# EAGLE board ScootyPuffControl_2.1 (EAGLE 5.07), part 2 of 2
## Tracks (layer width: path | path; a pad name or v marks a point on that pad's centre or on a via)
+5V  (via drill 0.41 pad 0.81, 0.61 pad 0.81)
  Top 0.254: R110.2 83.4,35.24 v81.92,35.24 | IC102.19 102.29,25.35 107,20.64 107,16.51 106.36,15.88 100.97,15.88 100.33,15.24 | 83.72,22.54 R310.2
  Top 0.305: R111.2 R112.2 R113.2 R108.2 R109.2 R110.2 | v85.09,27.3 81.92,27.3 81.28,26.67 81.28,26.04 79.75,24.5 IC305.8 79.75,22.54 | IC305.7 79.09,22.54 79.75,22.54 | 79.75,22.54 83.72,22.54 | R309.2 74.83,20.74 73.66,21.91 73.34,21.91
  Top 0.406: IC303.1 64.77,43.82 63.82,44.77 62.55,44.77 61.91,44.13 61.01,44.13 C306.2 60.59,43.81 v58.74,43.81
  Top 0.61: C306.2 60.28,44.13 | J100.P$36 99.06,92.71 v97.79,92.71 96.52,92.71 J100.P$34 | v101.6,81.28 99.69,79.38 99.69,55.24 v97.16,52.7 | J103.P$6 100.33,15.24 99.06,16.51 99.06,26.67 98.42,27.3 v97.16,27.3 88.27,27.3 IC301.4 | J102.P$6 54.61,15.24 55.24,15.88 60.96,15.88 61.59,16.51 v61.59,20.95 62.23,21.59 73.03,21.59 73.34,21.91 73.66,22.23 73.66,28.57 76.2,31.11 81.92,31.11 83.19,29.84 83.14,29.84 C305.+
  Top 1.016: IC301.2 88.27,27.3 88.27,28.57 | 88.27,28.57 IC301.4 | C305.+ 85.13,29.8 86.36,28.57 88.27,28.57
  Bottom 0.305: R304.2 78.72,56.52 77.79,56.52 77.15,57.15 75.56,57.15 72.39,53.98 69.22,53.98 65.41,50.16 60.64,50.16 58.74,48.26 v58.74,43.81
  Bottom 0.406: v90.81,29.21 92.08,29.21 92.08,29.84 | v58.74,43.81 59.69,42.86 59.69,40.64 58.42,39.37 58.42,28.57 57.15,27.3 57.15,23.81 59.69,20.95 v61.59,20.95
  Bottom 0.61: v97.79,92.71 100.33,92.71 101.6,91.44 v101.6,81.28 | v97.16,27.3 v97.16,52.7
  Bottom 1.016: 80.64,25.4 80.64,42.23 91.44,42.23 91.44,29.84 92.08,29.84 99.69,29.84 99.69,25.4 80.64,25.4
  other vias: 85.09,29.21 87,27.3 88.9,27.3 90.81,27.3 87,29.21 88.9,29.21
  pour Top (isolate 0.61, no thermals): 99.69,21.91 85.41,21.91 85.41,23.81 81.28,23.81 81.28,32.07 99.69,32.07
  pour Bottom: 80.64,26.04 80.64,41.91 90.81,41.91 90.81,29.84 91.44,29.21 99.06,29.21 99.06,26.04
+12V  (via drill 0.41 pad 0.81, 0.61 pad 0.81)
  Top 0.61: IC201.5 37.15,19.68 37.47,19.37 37.47,13.97 C201.2 D201.A 35.1,12.24 | IC221.5 36.83,76.83 37.47,76.2 37.47,71.53 C221.2 D221.A 34.92,70.94 33.66,69.85 v26.67,69.85 | v26.67,41.27 33.66,41.27 35.1,42.73 D211.A C211.2 37.47,42.77 37.47,47.62 36.83,48.26 IC211.5 | v26.67,14.61 29.21,12.06 34.92,12.06 35.1,12.24 | D6.A 113.48,95.3 C251.2 | IC231.5 123.19,36.83 122.56,37.47 122.56,41.68 C241.2 D231.A 124.92,43.63 125.41,44.13 v133.67,44.13 | 124.78,71.12 C231.2 122.56,70.89 122.56,66.04 123.19,65.41 IC241.5 | 124.78,71.12 D5.A | IC251.5 123.19,93.98 122.56,94.61 v122.56,97.79 | v133.67,72.71 125.09,72.71 124.78,72.39 124.78,71.12 | 35.1,12.24 35.1,12.06 43.18,12.06 43.18,12.7 C261.+ 43.2,14.63 43.81,15.24 50.8,15.24 52.07,13.97 v52.07,12.06 | 123.8,12.06 C262.+ 125.12,12.06 | v62.87,13.34 62.87,20 63.5,20.64 73.66,20.64 74.3,20 74.3,13.97 74.93,13.34 J303.6 77.47,15.24 78.11,15.88 81.92,15.88 82.55,15.24 J303.2
  Top 1.016: D6.A v111.76,97.79 93.98,97.79 | J100.P$30 91.44,97.79 93.98,97.79 | 93.98,97.79 J100.P$32 | v107.95,12.06 123.8,12.06 | v133.67,13.34 132.4,12.06 125.12,12.06 | v97.16,13.34 97.16,19.68 96.52,20.32 | 96.52,20.32 87,20.32 85.72,19.05 85.72,13.97 85.09,13.34 J303.2 | R303.2 96.37,22.07 96.52,21.59 96.52,20.32
  Bottom 0.61: v26.67,69.85 v26.67,41.27 v26.67,14.61 | 122.56,98.74 v122.56,97.79 | v62.87,13.34 53.34,13.34 v52.07,12.06
  Bottom 1.016: v133.67,13.34 v133.67,44.13 v133.67,72.71 133.67,97.47 132.4,98.74 122.56,98.74 112.71,98.74 v111.76,97.79 | v107.95,12.06 106.68,13.34 106.05,13.34 v97.16,13.34
AD0
  Top 0.254: IC101.98 67.94,64.68 67.94,73.03 | IC108.1 70.17,83.39 70.17,82.87 69.85,82.55 69.22,82.55 68.88,82.22 IC108.4 68.88,79.95 C117.1 69.93,79.61 70.17,79.38 70.17,77.15 67.94,74.93 67.94,73.03 | 67.94,73.03 67.94,73.34
AD1
  Top 0.254: IC101.99 67.31,64.61 67.31,76.52 67.63,76.83 67.63,79.38 67.39,79.61 C116.1 66.58,79.71 66.34,79.71 IC107.4 66.34,82.22 66.67,82.55 67.31,82.55 67.63,82.87 67.63,83.39 IC107.1
AD2
  Top 0.254: IC101.100 66.67,64.54 66.67,75.88 65.09,77.47 65.09,79.38 64.85,79.61 C115.1 63.8,79.95 IC106.4 63.8,82.22 64.14,82.55 64.77,82.55 65.09,82.87 65.09,83.39 IC106.1
AD3
  Top 0.254: IC101.1 69.62,57.78 67.94,57.78 66.04,59.69 66.04,75.56 64.77,76.83 63.5,76.83 62.55,77.79 62.55,79.38 62.31,79.61 C114.1 61.26,79.95 IC105.4 61.26,82.22 61.59,82.55 62.23,82.55 62.55,82.87 62.55,83.39 IC105.1
AD4
  Top 0.254: IC101.2 69.69,57.15 67.63,57.15 65.41,59.37 65.41,75.25 64.45,76.2 60.96,76.2 60.01,77.15 60.01,79.38 59.77,79.61 C113.1 59.05,79.69 58.72,80.03 IC104.4 58.72,82.22 59.05,82.55 59.69,82.55 60.01,82.87 60.01,83.39 IC104.1
AD5
  Top 0.203: 56.18,81.58 56.5,81.58 56.83,81.92 56.83,82.07 57.47,82.71 57.47,83.39
  Top 0.254: IC101.5 70.54,55.88 67.94,55.88 64.77,59.05 64.77,74.93 64.14,75.56 58.42,75.56 57.47,76.52 57.47,79.38 57.23,79.61 C112.1 56.52,79.69 56.18,80.03 56.18,81.58 IC103.4 | 57.47,83.39 IC103.1
AVCC  (via drill 0.41 pad 0.81)
  Top 0.254: IC101.4 73.01,59.05 v72.71,58.74 73.03,59.05 v73.03,60.96 73.03,62.43 IC101.94
  Top 0.305: v72.71,58.74 74.3,58.74 75.56,60.01 v79.38,60.01
  Bottom 0.254: v73.03,60.96 73.03,61.1
  Bottom 0.305: IC304.5 81.06,59.91 80.33,60.64 80.01,60.64 v79.38,60.01
  Bottom 0.406: v72.71,58.74 73.34,58.1 73.34,57.32 C109.2 71.42,55.4 69.37,55.4 68.2,56.58 C309.+ | 73.03,61.1 C110.2
EXT_INT  (via drill 0.41 pad 0.81)
  Top 0.254: IC101.22 75.88,49.2 v75.88,47.62
  Top 0.305: J303.5 v77.47,20.64 | R308.1 75.88,46.14 v75.88,47.62
  Bottom 0.305: v75.88,47.62 75.88,28.89 77.47,27.3 v77.47,20.64
GND  (via drill 0.41 pad 0.81, 0.61 pad 0.81)  (1 unrouted)
  Top 0.254: v83.82,63.5 IC101.63 | IC101.23 79.38,51.98 v79.38,53.34 | IC101.84 77.47,65.06 v77.47,64.77 74.45,61.75 | IC101.53 87.72,60.33 v87.63,59.69 | IC101.73 80.64,67.4 v80.64,66.67 | IC101.13 76.2,55.88 v76.83,55.88 | IC101.43 86.08,57.15 v85.72,57.15 | v81.92,53.34 82.82,53.34 IC101.33 88.05,48.11 R114.1 | v73.98,59.69 73.98,61.28 74.45,61.75 | IC101.3 71.75,58.51 v71.75,59.69 | v56.83,85.09 IC103.2 56.83,82.87 56.52,82.55 55.88,82.55 55.56,82.23 55.56,77.79 | v59.37,85.09 IC104.2 | v61.91,85.09 IC105.2 | v64.45,85.09 IC106.2 | v66.99,85.09 IC107.2 | v69.53,85.09 IC108.2 | 55.56,77.79 55.56,77.47 54.29,76.2 IC222.2 | C113.2 58.34,77.86 58.1,78.11 58.1,80.01 v57.78,80.33 | C114.2 60.88,77.86 60.64,78.11 60.64,80.01 v60.33,80.33 | C115.2 63.42,77.86 63.18,78.11 63.18,80.01 v62.87,80.33 | C116.2 65.96,77.86 65.72,78.11 65.72,80.01 v65.41,80.33 | C117.2 68.5,77.86 68.26,78.11 68.26,80.01 v67.94,80.33 | C112.2 55.64,77.86 55.56,77.79 | C204.1 v64.14,51.75 | C214.1 v64.14,54.29 | C1.1 v64.14,56.83 | IC203.2 56.52,52.07 v55.56,53.02 | IC2.2 56.52,57.15 v55.56,58.1 | IC213.2 56.52,54.61 v55.56,55.56 | v52.07,54.29 C213.1 | IC233.2 101.6,62.23 100.97,61.59 100.97,58.74 101.52,58.18 C233.1 103.43,58.18 | 103.43,58.18 C243.1 106.05,58.18 | 106.05,58.18 C253.1 | 106.05,58.18 106.05,62.02 106.68,62.65 IC253.2 | IC243.2 104.14,62.65 103.5,62.02 103.5,58.26 103.43,58.18 | IC101.93 74.41,61.75 74.45,61.75
  Top 0.305: 42.55,46.99 42.55,48.58 41.59,49.53 v34.61,49.53 | IC211.3 42.55,46.99 | IC212.2 46.04,47.62 45.72,47.31 45.72,46.04 45.4,45.72 43.18,45.72 42.55,46.35 42.55,46.99 | IC222.2 46.04,76.2 45.72,75.88 45.72,74.61 45.4,74.3 43.18,74.3 42.55,74.93 42.55,75.56 | IC221.3 42.55,75.56 | v34.61,20.95 41.59,20.95 42.55,20 42.55,18.41 | IC202.2 46.35,19.05 45.72,18.41 45.72,17.78 45.09,17.14 43.18,17.14 42.55,17.78 42.55,18.41 | IC232.2 113.98,37.47 114.3,37.78 114.3,38.73 114.62,39.05 117.16,39.05 117.47,38.73 117.47,38.1 | 117.47,38.1 117.47,36.51 118.43,35.56 v125.73,35.56 | IC231.3 117.47,38.1 | IC242.2 113.98,66.04 114.3,66.36 114.3,67.31 114.62,67.63 117.16,67.63 117.47,67.31 117.47,66.67 | 117.47,66.67 117.47,65.09 118.43,64.14 v125.73,64.14 | 117.47,66.67 IC241.3 | 42.55,18.41 IC201.3 | v116.84,82.55 LED104.C | 48.9,97.79 C111.1 | 42.55,75.56 42.55,77.15 41.59,78.11 v34.61,78.11 | IC102.11 97.09,36.45 96.52,35.88 v95.25,35.88 | C203.1 v52.07,51.75 | v52.07,56.83 C223.1 | C253.1 v107.31,56.52 | C234.1 C244.1 C254.1 106.68,73.03 v106.05,73.66 | v99.69,52.7 102.23,55.24 C233.1 | 105.63,13.55 J103.P$2 105.95,13.87 LED108.C LED107.C LED303.C | IC305.1 79.75,25.77 79.06,25.08 v75.56,25.08 | J104.GND1 64.13,22.86 v64.77,22.86 | J104.GND2 71.24,22.86 v69.22,22.86
  Top 0.406: 127,80.64 127,80.01 v126.36,79.38 | v110.49,90.17 IC252.2 | 67.63,44.77 C307.- 67.08,45.72 IC303.3 65.75,46.01 65.09,46.67 62.55,46.67 61.91,46.04 60.91,46.04 C306.1 60.37,46.04 | 67.63,44.77 IC303.2 | v33.66,34.29 33.66,33.66 38.73,33.66 40.64,31.75 LED101.C | LED102.C 40.64,60.33 38.73,62.23 34.29,62.23 v33.66,62.87 | v33.66,91.44 34.29,90.81 38.73,90.81 40.64,88.9 LED103.C | v126.36,22.23 125.73,22.86 121.28,22.86 119.38,24.77 LED106.C | LED105.C 119.38,53.34 121.28,51.44 125.73,51.44 v126.36,50.8 | C251.1 116.44,94.84 v115.57,93.98 | 67.63,44.77 68.9,44.77 v69.85,45.72 | v69.85,37.47 69.85,36.37 arc90 J104.GND4 69.83,36.2 68.58,36.2 68.33,35.94 J104.6 | J104.GND3 arc90 63.5,36.37 v63.5,37.47 | v58.42,26.67 C118.1
  Top 0.61: v33.66,38.1 33.66,38.73 34.29,39.37 37.47,39.37 38.73,40.64 38.73,42.55 | IC221.3 39.37,75.56 38.73,74.93 38.73,71.12 | IC211.3 39.37,46.99 38.73,46.35 38.73,42.55 | 38.73,71.12 38.73,69.22 37.47,67.94 34.92,67.94 v33.66,66.67 | 38.73,71.12 C221.1 | 38.73,42.55 C211.1 | C201.1 40.01,13.97 38.73,15.24 38.73,17.78 39.37,18.41 IC201.3 | C251.1 IC251.3 | 55.88,97.79 58.42,97.79 | 58.42,97.79 60.96,97.79 | 60.96,97.79 63.5,97.79 | 63.5,97.79 66.04,97.79 | 66.04,97.79 68.58,97.79 | 58.42,97.79 J100.P$4 | 60.96,97.79 J100.P$6 | 63.5,97.79 J100.P$8 | 66.04,97.79 J100.P$10 | 68.58,97.79 J100.P$12 | 68.58,97.79 86.36,97.79 | 86.36,97.79 J100.P$26 | J100.P$28 88.9,97.79 86.36,97.79 | 55.88,97.79 J100.P$2 | 55.88,97.79 48.9,97.79 38.1,97.79 35.56,95.25 v33.66,95.25 | IC241.3 120.65,66.67 121.28,67.31 121.28,71.12 | 121.28,71.12 121.28,72.39 123.83,74.93 125.73,74.93 v126.36,75.56 | 121.28,71.12 C231.1 | IC231.3 120.65,38.1 121.28,38.73 121.28,42.55 | 121.28,42.55 121.28,43.81 124.46,46.99 v126.36,46.99 | 121.28,42.55 C241.1 | v46.99,12.7 C261.- | v59.69,11.75 J102.P$2 | v105.41,11.75 J103.P$2 | v80.01,14.61 J303.4 | v93.34,31.75 v98.74,31.75
  Top 1.016: C305.- 83.22,24.84 IC301.1 85.95,22.95 v85.94,21.59 | C304.- v93.34,31.75
  Bottom 0.254: 79.38,49.9 C105.1 | 76.69,55.88 v76.83,55.88 79.38,55.88 79.38,53.98 | C106.1 83.19,53.2 | v85.72,57.15 85.72,57.01 | 89.81,59.05 C103.1 | 80.64,68.85 C101.1 | v80.64,66.67 80.33,65.09 81.92,63.5 v83.82,63.5 83.82,61.59 86.04,59.37 | v87.63,59.69 86.36,59.69 86.04,59.37 | 86.04,59.37 85.27,58.6 85.27,57.6 v85.72,57.15 | 81.28,53.98 v81.92,53.34 | 81.28,53.98 79.38,53.98 | 79.38,53.98 v79.38,53.34 | v85.72,57.15 83.82,57.15 81.28,54.61 81.28,53.98 | 71.61,59.69 v71.75,59.69 v73.98,59.69 | v56.83,85.09 v59.37,85.09 v61.91,85.09 v64.45,85.09 v66.99,85.09 v69.53,85.09 69.53,80.96 68.9,80.33 v67.94,80.33 v65.41,80.33 v62.87,80.33 v60.33,80.33 v57.78,80.33 | v52.07,54.29 54.29,54.29 v55.56,55.56
  Bottom 0.305: 32.7,92.08 v31.75,93.34 | 127.32,18.41 v126.36,18.41 | 127.32,46.99 v126.36,46.99 | 127.32,79.38 v126.36,79.38 | C308.1 83.56,60.22 83.56,61.37 | 83.56,61.37 82.53,62.4 81.32,62.4 IC304.3 | v52.07,51.75 v52.07,54.29 v52.07,56.83 | v106.05,73.66 107.95,71.75 107.95,67.94 107.31,67.31 107.31,59.45 107.31,57.15 v107.31,56.52 | C309.- 68.29,60.89 | 79.75,63.97 78.94,64.77 v77.47,64.77 | 83.56,61.37 83.79,61.59 83.82,61.59
  Bottom 0.406: 32.7,20.95 v34.61,20.95 | IC304.2 79.07,63.3 79.75,63.97 IC304.3 | 127.32,91.44 127.06,94.05 | 127.06,94.05 127,94.61 | v110.49,90.17 110.49,88.58 111.12,87.95 111.12,83.82 112.39,82.55 v116.84,82.55 118.75,82.55 121.28,80.01 125.73,80.01 v126.36,79.38 | v79.38,53.34 79.38,49.9 | 76.69,55.88 C108.1 | 85.72,57.01 C102.1 | 89.81,59.05 88.27,59.05 v87.63,59.69 | C106.1 83.04,53.34 v81.92,53.34 | v80.64,66.67 80.64,68.85 | C107.1 76.69,64.77 v77.47,64.77 | C104.1 84.6,63.5 v83.82,63.5 | C110.1 71.61,59.69 71.61,58.42 C109.1 | C105.1 79.06,50.12 | v115.57,93.98 117.16,93.98 118.11,94.93 126.17,94.93 127.06,94.05 | 79.38,5.71 78.74,6.35
  Bottom 0.61: v33.66,34.29 33.66,31.43 32.7,31.11 | 39.37,5.71 43.18,5.71 43.81,6.35 | 32.7,66.67 v33.66,66.67 | 85.09,5.71 J302.P$4 | 63.5,5.71 64.14,6.35 | 105.41,5.71 v105.41,11.75 | 32.7,88.27 32.72,88.28 | 46.99,5.71 v46.99,12.7 | 123.19,12.7 123.19,8.89 123.35,8.73 | 80.01,5.71 v80.01,14.61
  Bottom 1.016: 59.69,5.71 v59.69,11.75 | 44.45,5.71 43.81,5.08 | v85.94,21.59 87.95,18.73 J302.P$6
  Bottom 10.16: 32.7,92.08 32.7,88.27 32.7,66.67 32.7,31.11 32.7,20.95 32.7,13.02 39.37,5.71 44.45,5.71 46.99,5.71 59.69,5.71 63.5,5.71 79.38,5.71 80.01,5.71 85.09,5.71 105.41,5.71 120.33,5.71 123.35,8.73 127.32,12.7 127.32,18.41 127.32,46.99 127.32,79.38 127.32,91.44
  other vias: 33.66,93.34 31.75,95.25 31.75,36.2 33.66,36.2 31.75,38.1 31.75,62.87 31.75,64.77 33.66,64.77 31.75,91.44 31.75,66.67 31.75,34.29 128.27,46.99 126.36,48.9 128.27,48.9 128.27,50.8 128.27,75.56 126.36,77.47 128.27,77.47 128.27,79.38 128.27,18.41 126.36,20.32 128.27,20.32 128.27,22.23
  pour Top (isolate 0.305, no thermals): 25.4,96.52 36.83,96.52 36.83,90.17 25.4,90.17
  pour Top (isolate 0.305, no thermals): 25.4,39.37 36.83,39.37 36.83,33.02 25.4,33.02
  pour Top (isolate 0.305, no thermals): 25.4,67.94 36.83,67.94 36.83,61.59 25.4,61.59
  pour Bottom (no thermals): 87,19.68 87,12.7 85.09,10.79 85.09,1.27 97.79,1.27 97.79,10.16 95.89,12.7 95.89,19.68
  pour Top (isolate 0.305, no thermals): 134.62,17.14 123.19,17.14 123.19,23.5 134.62,23.5
  pour Top (isolate 0.305, no thermals): 134.62,45.72 123.19,45.72 123.19,52.07 134.62,52.07
  pour Top (isolate 0.305, no thermals): 134.62,74.3 123.19,74.3 123.19,80.64 134.62,80.64
  pour Bottom (isolate 0.61): 27.94,16.51 27.94,99.06 132.08,99.06 132.08,20.95 121.92,10.79 109.86,10.79 59.05,9.53 49.53,10.16 34.29,10.16
  pour Top (no thermals): 87.63,19.05 87.63,11.43 95.25,11.43 95.25,19.05
HA1  (via drill 0.41 pad 0.81)
  Top 0.254: IC102.3 101.64,46.63 100.97,47.31 96.84,47.31 v95.89,48.26 | IC101.59 90.81,67.66 v91.44,68.26
  Bottom 0.254: v91.44,68.26 94.93,68.26 95.89,67.31 v95.89,48.26
HA2  (via drill 0.41 pad 0.81)
  Top 0.254: IC101.58 90.53,66.67 v91.44,66.67 | IC102.4 100.99,46.02 100.33,46.67 95.57,46.67 v94.61,47.62
  Bottom 0.254: 90.81,66.67 v91.44,66.67 93.66,66.67 95.25,65.09 95.25,53.34 94.61,52.7 v94.61,47.62
HA3  (via drill 0.41 pad 0.81)
  Top 0.254: IC102.5 100.34,45.4 99.69,46.04 94.3,46.04 v93.66,46.67 | IC101.57 89.97,65.41 v91.44,65.41
  Bottom 0.254: v91.44,65.41 93.03,65.41 94.61,63.82 94.61,53.98 93.66,53.02 v93.66,46.67
HB1  (via drill 0.41 pad 0.81)
  Top 0.254: IC102.6 99.69,44.77 99.06,45.4 92.71,45.4 v91.12,46.99 | IC101.62 87,65.97 v87,67.94
  Bottom 0.254: v91.12,46.99 91.12,53.34 92.71,54.93 92.71,61.59 92.08,62.23 91.12,62.23 87,66.36 v87,67.94
HB2  (via drill 0.41 pad 0.81)
  Top 0.254: IC101.61 88.27,66.53 v88.27,68.58 | IC102.7 99.04,44.16 98.42,44.77 91.76,44.77 v91.12,45.4
  Bottom 0.254: v91.12,45.4 92.08,46.35 92.08,53.34 93.34,54.61 93.34,62.23 92.71,62.87 91.44,62.87 88.27,66.04 v88.27,68.58
HB3  (via drill 0.41 pad 0.81)
  Top 0.254: IC102.8 98.39,43.85 98.11,44.13 91.44,44.13 v91.12,43.81 | IC101.60 89.53,67.09 v89.53,69.22
  Bottom 0.254: v89.53,69.22 89.53,65.72 91.76,63.5 93.03,63.5 93.98,62.55 93.98,54.29 92.71,53.02 92.71,45.4 v91.12,43.81
IU1
  Top 0.254: C204.2 60.64,52.34 60.64,52.39 60.96,52.7 64.77,52.7 66.04,53.98 70.76,53.98 IC101.8 | C204.2 60.64,52.02 | IC203.1 57.34,52.72 IC203.4 60.39,51.42 C204.2
IU2  (via drill 0.41 pad 0.81)
  Top 0.254: IC101.95 69.85,64.9 69.85,71.75 v70.48,72.39 | IC233.1 100.95,63.69 IC233.4 102.25,66.03 v102.23,66.04
  Top 0.305: v101.6,68.58 C234.2
  Bottom 0.305: v70.48,72.39 100.97,72.39 102.23,71.12 102.23,68.58 | 102.23,68.58 v102.23,66.04 | 102.23,68.58 v101.6,68.58
IV1
  Top 0.254: IC213.1 57.45,55.26 58.63,54.08 IC213.4 60.63,53.96 60.64,53.98 60.64,54.56 C214.2 60.59,54.88 60.96,55.24 65.72,55.24 66.36,54.61 70.69,54.61 IC101.7
IV2  (via drill 0.41 pad 0.81)
  Top 0.254: IC101.96 69.22,64.83 69.22,72.39 v70.48,73.66 | IC243.1 103.49,63.69 IC243.4 104.79,66.03 v104.78,66.04
  Top 0.305: v104.14,68.58 C244.2
  Bottom 0.305: 104.78,68.58 104.78,71.12 102.23,73.66 v70.48,73.66 | 104.78,68.58 v104.78,66.04 | 104.78,68.58 v104.14,68.58
IW1
  Top 0.254: C1.2 60.59,56.88 | C1.2 60.59,57.42 60.96,57.78 65.09,57.78 67.63,55.24 70.61,55.24 IC101.6 | C1.2 60.64,57.1 60.64,56.52 60.63,56.5 IC2.4 57.34,57.8 IC2.1
IW2  (via drill 0.41 pad 0.81)
  Top 0.254: IC101.97 68.58,64.76 68.58,73.03 v70.48,74.93 | IC253.1 106.03,63.69 IC253.4
  Top 0.305: IC253.4 107.31,65 107.31,66.04 106.68,66.67 v106.68,68.58 C254.2
  Bottom 0.254: 103.5,74.93 106.05,72.39
  Bottom 0.305: v70.48,74.93 103.5,74.93 | 106.05,72.39 106.68,71.75 v106.68,68.58
LED1
  Top 0.254: IC101.72 83.19,69.23 83.19,69.85 81.92,71.12 81.28,71.12 80.33,72.07 R101.2
LED2
  Top 0.254: IC101.71 83.82,69.16 83.82,70.17 82.55,71.44 R102.2
LED3
  Top 0.254: IC101.70 84.2,68.83 | 84.2,68.83 84.45,69.08 | R103.2 84.77,69.4 84.2,68.83
LED4
  Top 0.254: R104.2 87,70.92 IC101.69
LED5
  Top 0.254: R105.2 89.22,71.44 88.9,71.12 87.9,71.12 IC101.68
LED6
  Top 0.254: R106.2 91.44,71.12 90.81,70.48 87.98,70.48 IC101.67
LED7  (via drill 0.41 pad 0.81)
  Top 0.254: IC101.41 88.48,53.34 v89.22,53.34
  Top 0.305: v105.41,25.4 109.22,25.4 110.17,24.45 R116.2
  Bottom 0.254: v89.22,53.34 86.36,50.48 86.36,49.53 79.69,42.86 79.69,24.77 80.33,24.13 104.14,24.13 v105.41,25.4
LED8  (via drill 0.41 pad 0.81)
  Top 0.254: IC101.42 87.92,54.61 v88.58,54.61
  Top 0.305: v105.41,23.5 107.63,23.5 108.27,22.86 R117.2
  Bottom 0.254: v88.58,54.61 85.72,51.75 85.72,49.85 79.06,43.18 79.06,24.45 80.01,23.5 v105.41,23.5
MISO  (via drill 0.41 pad 0.81)
  Top 0.254: J104.7 69.42,32.81 69.85,32.38 70.8,32.38 71.75,33.34 71.75,36.2 73.34,37.78 81.28,37.78 86.36,42.86 R115.1 87.95,42.86 87.63,43.18 v87.63,45.72 | IC101.31 85.72,49.02 v85.72,45.72
  Bottom 0.254: v87.63,45.72 v85.72,45.72
MOSI
  Top 0.254: J104.3 65.03,37.72 66.36,39.05 80.64,39.05 84.77,43.18 84.77,49.27 IC101.30
N$1
  Top 0.305: LED107.A R116.1
N$2
  Top 0.305: LED108.A R117.1
N$4
  Top 0.61: IC201.7 31.11,17.14 30.48,16.51 30.48,15.66 R201.1
N$5  (via drill 0.41 pad 0.81)
  Top 0.61: v38.73,19.68 IC201.4 | v38.73,31.75 R202.1
  Bottom 0.61: v38.73,19.68 v38.73,31.75
N$6  (via drill 0.41 pad 0.81)
  Top 0.61: v38.73,48.26 IC211.4 | v38.73,60.33 R212.1
  Bottom 0.61: v38.73,48.26 v38.73,60.33
N$7
  Top 0.61: R211.1 30.38,44.98 31.11,45.72 IC211.7
N$8
  Top 0.305: LED303.A R307.1
N$9  (via drill 0.41 pad 0.81)
  Top 0.61: v38.73,76.83 IC221.4 | v38.73,88.9 R222.1
  Bottom 0.61: v38.73,76.83 v38.73,88.9
N$10
  Top 0.61: IC221.7 31.11,74.3 30.48,73.66 30.48,72.49 R221.1
N$11
  Top 0.61: IC211.8 32.62,44.45 C212.2 32.2,44.04 D211.C
N$12
  Top 0.61: IC201.8 32.62,15.88 C202.2 32.38,13.97 D201.C
N$14
  Top 0.61: 33.02,73.03 31.98,73.03 C222.2 | 33.02,73.03 IC221.8 | D221.C 32.2,72.84 33.02,73.03
N$21
  Top 0.254: IC107.3 66.34,84.47 66.04,84.77 J100.P$9
N$30
  Top 0.254: 82.55,20.64 82.65,20.74
  Top 0.305: IC305.6 78.44,22.2 79.06,21.59 81.92,21.59 82.55,20.95 82.55,20.64 J303.1 | 82.65,20.74 R310.1
N$33
  Top 1.016: IC301.3 93.31,24.84 C304.+ 96.41,24.8 R303.1
N$34
  Bottom 0.305: IC304.1 79.75,61.28 80.64,61.28 82.44,59.48 82.44,59.03 82.86,58.62 C308.2
  Bottom 0.406: C308.2 81.39,56.63 R304.1
N$35
  Top 0.254: IC102.18 101.64,40.6 101.28,40.96 86.68,40.96 83.5,37.78 R110.1
  Top 0.305: J103.P$1 105.41,20.95 101.64,24.73 IC102.18
N$36
  Top 0.254: IC102.16 100.34,39.36 100.01,39.69 89.22,39.69 87.31,37.78 R108.1
  Top 0.305: IC102.16 100.34,18.42 J103.P$5
N$37
  Top 0.254: IC102.17 100.99,39.98 100.65,40.32 87.95,40.32 85.41,37.78 R109.1
  Top 0.305: J103.P$3 102.87,22.23 100.99,24.11 IC102.17
N$39
  Top 0.254: IC102.15 99.69,38.74 99.38,39.05 90.49,39.05 89.22,37.78 R113.1
  Top 0.305: IC102.15 99.69,33.97 98.74,33.02 76.2,33.02 72.39,29.21 61.59,29.21 60.96,28.57 60.96,24.13 59.69,22.86 J102.P$1
N$40
  Top 0.254: IC102.14 99.04,38.12 98.74,38.42 91.76,38.42 91.12,37.78 R112.1
  Top 0.305: IC102.14 99.04,34.59 98.11,33.66 75.56,33.66 71.75,29.84 60.96,29.84 60.33,29.21 60.33,24.45 57.15,21.27 J102.P$3
N$41
  Top 0.305: IC102.13 98.39,35.2 97.47,34.29 94.3,34.29 | J102.P$5 54.61,20.32 59.69,25.4 59.69,29.84 60.33,30.48 71.12,30.48 74.93,34.29 94.3,34.29 | R111.1 94.08,37.05 94.3,36.83 94.3,34.29
N$42
  Top 0.61: IC231.7 128.91,39.37 129.54,40.01 129.54,41.17 R231.1
N$43  (via drill 0.41 pad 0.81)
  Top 0.61: v121.28,36.83 IC231.4 | v121.28,24.77 R232.1
  Bottom 0.61: v121.28,24.77 v121.28,36.83
N$44  (via drill 0.41 pad 0.81)
  Top 0.61: v121.28,65.41 IC241.4 | v121.28,53.34 R242.1
  Bottom 0.61: v121.28,53.34 v121.28,65.41
N$45
  Top 0.61: IC241.7 128.91,67.94 129.54,68.58 129.54,69.75 R241.1
N$46  (via drill 0.41 pad 0.81)
  Top 0.61: v121.28,93.98 IC251.4 | v121.28,81.92 R252.1
  Bottom 0.61: v121.28,81.92 v121.28,93.98
N$47
  Top 0.61: IC251.7 128.91,96.52 129.54,97.16 129.54,98.32 R251.1
N$48
  Top 0.61: IC231.8 127.41,40.64 C232.2 127.81,41.05 D231.C
N$49
  Top 0.61: IC241.8 127.41,69.22 C242.2 127.81,69.62 D5.C
N$50
  Top 0.61: C252.2 127.41,97.79 IC251.8 124.46,97.85 124.46,98.42 123.83,99.06 116.84,99.06 116.39,98.61 D6.C
N$51
  Top 0.61: T201.G 28.68,17.14 R201.2
N$52
  Top 0.61: T202.G R202.2
N$53
  Top 0.61: R211.2 28.68,45.62 28.57,45.72 T211.G
N$54
  Top 0.61: T212.G R212.2
N$55
  Top 0.61: R221.2 28.68,74.19 28.57,74.3 T221.G
N$56
  Top 0.61: T222.G R222.2
N$57
  Top 0.61: R232.2 T8.G
N$58
  Top 0.61: R231.2 131.34,39.47 131.44,39.37 T231.G
N$59
  Top 0.61: R241.2 131.34,68.05 131.44,67.94 T241.G
N$60
  Top 0.61: R242.2 T242.G
N$61
  Top 0.61: R251.2 131.34,96.62 131.44,96.52 T251.G
N$62
  Top 0.61: R252.2 T252.G
N$63  (via drill 0.41 pad 0.81)
  Top 0.254: v46.99,33.66 46.99,31.97 LED101.A
  Top 0.305: v80.33,76.83 R101.1
  Bottom 0.254: v46.99,33.66 46.99,39.37
  Bottom 0.305: v80.33,76.83 79.69,77.47 55.88,77.47 55.24,76.83 55.24,62.23 50.8,57.78 50.8,51.44 52.07,50.16 52.07,48.9 49.21,46.04 49.21,41.91 46.99,39.69 46.99,39.37
N$64
  Top 0.254: IC108.3 68.88,84.47 68.58,84.77 J100.P$11
N$65
  Top 0.254: IC106.3 63.8,84.47 63.5,84.77 J100.P$7
N$66
  Top 0.254: IC105.3 61.26,84.47 60.96,84.77 J100.P$5
N$67
  Top 0.254: IC104.3 58.72,84.47 58.42,84.77 J100.P$3
N$68
  Top 0.254: IC103.3 56.18,84.15 55.88,84.45 J100.P$1
N$69  (via drill 0.41 pad 0.81)
  Top 0.254: IC233.3 102.23,63.28 v102.23,61.59
  Top 0.305: IC232.1 113,39.66 v113.03,39.69 | v102.23,61.59 C233.2
  Bottom 0.305: v113.03,39.69 102.23,50.48 v102.23,61.59
N$70  (via drill 0.41 pad 0.81)
  Top 0.305: v82.55,76.83 R102.1 | LED102.A 46.77,61.81 v46.67,61.91
  Bottom 0.305: v82.55,76.83 82.55,77.47 81.92,78.11 55.24,78.11 54.61,77.47 54.61,62.87 53.66,61.91 v46.67,61.91
N$71  (via drill 0.41 pad 0.81)
  Top 0.305: v84.77,76.83 R103.1 | v48.9,88.9 LED103.A
  Bottom 0.305: v84.77,76.83 84.77,78.11 84.14,78.74 57.15,78.74 55.88,80.01 55.88,84.45 54.61,85.72 50.16,85.72 48.9,87 v48.9,88.9
N$72  (via drill 0.41 pad 0.81)
  Top 0.305: R104.1 v87,76.83 | v113.35,80.96 113.35,82.45 LED104.A
  Bottom 0.305: v87,76.83 87,78.11 87.63,78.74 104.78,78.74 106.05,77.47 112.08,77.47 113.35,78.74 v113.35,80.96
N$73  (via drill 0.41 pad 0.81)
  Top 0.305: R105.1 v89.22,76.83 | v113.03,51.44 113.03,53.12 LED105.A
  Bottom 0.305: v89.22,76.83 89.22,77.79 89.53,78.11 104.14,78.11 109.22,73.03 109.22,55.24 v113.03,51.44
N$74  (via drill 0.41 pad 0.81)
  Top 0.305: v91.44,76.83 R106.1 | v113.03,22.86 113.03,24.55 LED106.A
  Bottom 0.305: v91.44,76.83 104.14,76.83 108.58,72.39 108.58,54.61 109.86,53.34 109.86,46.35 114.3,41.91 114.3,37.47 111.76,34.92 111.76,24.13 v113.03,22.86
N$75
  Top 0.254: 47.12,75.14 IC222.1 49.53,75.25 50.48,74.3 50.48,59.05 51.44,58.1 53.58,58.1 C223.2 55.18,56.5 IC2.3
N$76  (via drill 0.41 pad 0.81)
  Top 0.254: IC203.3 55.18,51.42 C203.2
  Top 0.305: IC202.1 v48.58,18.1 | v54.61,50.16 54.61,51.51 C203.2
  Bottom 0.305: v48.58,18.1 49.53,19.05 49.53,33.02 47.62,34.92 47.62,39.37 50.16,41.91 50.16,45.72 v54.61,50.16
N$77  (via drill 0.41 pad 0.81)
  Top 0.254: C243.2 104.79,61.2 IC243.3
  Top 0.305: v111.13,66.99 IC242.1 | v111.12,70.48 109.22,70.48 108.58,69.85 108.58,55.56 107.95,54.93 105.41,54.93 104.78,55.56 v104.78,56.52 | v104.78,61.59 C243.2
  Bottom 0.305: v111.13,66.99 v111.13,70.48 v111.12,70.48 | v104.78,56.52 v104.78,61.59
N$78
  Top 0.254: 77.8,21.9 77.8,22.44 R309.1
  Top 0.305: IC305.5 77.8,21.9 78.74,20.95 79.38,20.95 80.01,20.32 J303.3
N$80  (via drill 0.41 pad 0.81)
  Top 0.254: IC213.3 55.18,53.96 C213.2
  Top 0.305: IC212.1 47.02,45.12 v46.99,45.09 | C213.2 53.9,55.24 51.44,55.24 51.12,54.93 v51.12,49.53
  Bottom 0.305: v46.99,45.09 46.99,48.9 47.62,49.53 v51.12,49.53
N$81
  Top 0.254: IC253.3 107.31,63.28 C253.2
  Top 0.305: IC252.1 109.54,87.95 106.68,85.09 105.41,85.09 104.14,83.82 104.14,79.38 107.95,75.56 107.95,63.5 107.73,63.28 IC253.3
PDI  (1 unrouted)
  Top 0.254: IC101.89 72.39,66.6 72.39,86.36 71.12,87.63 J100.P$13
PF0
  Top 0.254: IC101.45 90.04,54.61 95.25,54.61 97.16,56.52 97.16,81.28 104.14,88.27 J100.P$39
PF1
  Top 0.254: IC101.46 90.11,55.24 94.61,55.24 96.52,57.15 96.52,81.92 101.6,87 J100.P$37
PF2
  Top 0.254: IC101.47 90.17,55.89 90.17,55.88 93.98,55.88 95.89,57.78 95.89,82.55 99.06,85.72 J100.P$35
PF3
  Top 0.254: IC101.48 90.26,56.52 93.34,56.52 95.25,58.42 95.25,83.19 96.52,84.45 J100.P$33
PF4
  Top 0.254: IC101.49 90.33,57.15 92.71,57.15 94.61,59.05 94.61,83.19 93.98,83.82 J100.P$31
PF5
  Top 0.254: IC101.50 90.4,57.78 92.08,57.78 93.98,59.69 93.98,82.55 91.44,85.09 J100.P$29
PF6
  Top 0.254: IC101.51 93.34,64.54 93.34,81.92 88.9,86.36 J100.P$27
PF7
  Top 0.254: IC101.52 92.71,64.61 92.71,81.28 86.36,87.63 J100.P$25
PK0
  Top 0.254: IC101.75 78.74,71.92 78.74,82.55 83.82,87.63 J100.P$23
PK1
  Top 0.254: IC101.76 78.11,70.08 78.11,83.19 82.55,87.63 82.55,91.44 83.82,92.71 J100.P$24
PK2
  Top 0.254: IC101.77 77.47,70.01 77.47,83.82 81.28,87.63 J100.P$21
PK3
  Top 0.254: IC101.78 76.83,69.94 76.83,84.45 80.01,87.63 80.01,91.44 81.28,92.71 J100.P$22
PK4
  Top 0.254: IC101.79 76.2,69.86 76.2,85.09 78.74,87.63 J100.P$19
PK5
  Top 0.254: IC101.80 75.56,69.79 75.56,85.72 77.47,87.63 77.47,91.44 78.74,92.71 J100.P$20
PK6
  Top 0.254: IC101.81 74.93,69.72 74.93,86.36 76.2,87.63 J100.P$17
PK7
  Top 0.254: J100.P$18 76.2,92.71 74.93,91.44 74.93,87.63 74.3,87 74.3,69.65 IC101.82
PQ2
  Top 0.254: IC101.87 73.66,66.75 J100.P$15
PQ3
  Top 0.254: J100.P$16 73.66,92.71 72.39,91.44 72.39,87.63 73.03,87 73.03,66.67 IC101.88
RESET  (via drill 0.41 pad 0.81)  (1 unrouted)
  Top 0.254: 70.48,92.08 69.85,91.44 69.85,87.63 71.75,85.72 71.75,76.2 | 70.48,92.08 71.12,92.71 J100.P$14 | IC101.90 71.75,66.53 71.75,76.2 | v70.48,76.2 71.75,76.2 | R107.1 49.11,92.08 70.48,92.08
  Top 0.305: R107.1 C111.2
  Bottom 0.305: v56.52,67.94 56.52,75.25 57.47,76.2 v70.48,76.2
SCK
  Top 0.254: J104.5 67.22,37.06 68.58,38.42 80.96,38.42 86.68,44.13 86.68,46.67 | IC101.32 86.68,48.78 86.68,46.67 | R114.2 89.75,46.89 89.53,46.67 86.68,46.67
SCL  (via drill 0.41 pad 0.81)
  Top 0.254: v81.92,47.62 81.92,49.3 IC101.26
  Top 0.305: IC305.3 78.42,27.08 78.42,28.57 78.11,28.89 v78.11,29.84 | R312.1 80.01,46.99 80.64,47.62 v81.92,47.62
  Bottom 0.305: v78.11,29.84 78.11,43.81 v81.92,47.62
SDA  (via drill 0.41 pad 0.81)
  Top 0.254: IC101.25 77.47,48.66 v77.47,47.62 77.47,44.77 76.83,44.13 R311.1
  Top 0.305: v76.83,29.21 77.79,28.26 77.79,27.06 IC305.4
  Bottom 0.305: v77.47,47.62 76.83,46.67 v76.83,29.21
SS
  Top 0.254: J104.2 63.92,32.81 63.82,32.7 62.23,32.7 61.59,33.34 61.59,38.42 62.87,39.69 80.33,39.69 84.14,43.5 84.14,45.94 | IC101.29 84.14,49.2 84.14,46.35 84.14,45.94 | 84.14,45.94 R118.1
U1  (via drill 0.61 pad 0.81)
  Top 0.305: 32.38,22.23 32.38,21.59 | 32.38,22.23 R204.P$1 | 32.38,22.23 34.92,22.23 35.56,21.59 41.91,21.59 43.5,20 IC202.4
  Top 0.61: IC201.6 32.62,18.41 C202.1
  other vias: 22.86,39.37 20.95,39.37 19.05,39.37 17.14,39.37 15.24,39.37 13.34,39.37 13.34,37.47 13.34,35.56 13.34,33.66 13.34,31.75 15.24,37.47 17.14,37.47 19.05,37.47 15.24,35.56 15.24,33.66 15.24,31.75 17.14,31.75 19.05,31.75 20.95,31.75 22.86,31.75 22.86,33.66 22.86,37.47 22.86,35.56 20.95,37.47 19.05,35.56 17.14,35.56 17.14,33.66 19.05,33.66 20.95,35.56 20.95,33.66
  pour Top (no thermals): 33.02,18.41 25.4,18.41 25.4,26.67 24.13,27.94 12.06,27.94 12.06,42.55 23.5,42.55 23.5,31.11 24.13,30.48 33.02,30.48
  pour Bottom (isolate 0.61, no thermals): 26.67,42.23 0,42.23 0,15.56 9.53,15.56 9.53,28.89 26.67,28.89
U1H
  Top 0.254: IC201.1 50.16,15.88 50.8,16.51 50.8,18.41 57.15,24.77 57.15,44.45 60.33,47.62 72.89,47.62 IC101.20
U1L
  Top 0.254: IC201.2 42.23,17.14 42.86,16.51 49.53,16.51 50.16,17.14 50.16,18.73 56.52,25.08 56.52,45.09 59.69,48.26 72.82,48.26 IC101.19
U1O
  Top 0.305: IC202.5 44.42,18.7 44.77,19.05 45.4,19.05 45.72,19.37 45.72,23.18 J_U1.P$4
  pour Top (no thermals): 36.83,30.48 36.83,22.23 47.62,22.23 47.62,30.48
U2  (via drill 0.61 pad 0.81)
  Top 0.305: IC232.4 116.52,36.52 118.11,34.92 124.46,34.92 125.41,33.97 126.68,33.97 R233.P$1 | C232.1 127.64,35.56
  Top 0.61: IC231.6 127.41,38.1 C232.1
  other vias: 137.16,17.14 139.06,17.14 140.97,17.14 142.88,17.14 144.78,17.14 146.69,17.14 146.69,19.05 146.69,20.95 146.69,22.86 146.69,24.77 144.78,19.05 142.88,19.05 140.97,19.05 144.78,20.95 144.78,22.86 144.78,24.77 142.88,24.77 140.97,24.77 139.06,24.77 137.16,24.77 137.16,22.86 137.16,19.05 137.16,20.95 139.06,19.05 140.97,20.95 142.88,20.95 142.88,22.86 140.97,22.86 139.06,20.95 139.06,22.86
  pour Top (no thermals): 127,38.1 134.62,38.1 134.62,29.84 135.89,28.57 147.96,28.57 147.96,15.88 147.32,15.24 136.53,15.24 136.53,25.4 135.89,26.04 127,26.04
  pour Bottom (isolate 0.61, no thermals): 120.02,0.32 160.02,0.32 160.02,27.62 133.35,27.62 133.35,19.05 120.02,5.71
U2H
  Top 0.254: IC101.36 88.44,49.85 111.76,49.85 112.71,48.9 112.71,42.23 114.3,40.64 IC231.1
U2L
  Top 0.254: IC101.35 88.37,49.21 111.44,49.21 112.08,48.58 112.08,41.91 113.98,40.01 117.16,40.01 117.79,39.37 IC231.2
U2O
  Top 0.305: J_U2.P$4 114.3,33.34 114.3,36.83 114.94,37.47 115.25,37.47 115.6,37.81 IC232.5
  pour Top (no thermals): 123.19,26.04 112.39,26.04 112.39,34.29 123.19,34.29
V1  (via drill 0.61 pad 0.81)
  Top 0.305: IC212.4 43.5,48.58 41.91,50.16 35.56,50.16 34.92,50.8 32.38,50.8 R213.P$1 | C212.1 32.38,50.16
  Top 0.61: IC211.6 32.62,46.99 C212.1
  other vias: 22.86,67.94 20.95,67.94 19.05,67.94 17.14,67.94 15.24,67.94 13.34,67.94 13.34,66.04 13.34,64.14 13.34,62.23 13.34,60.33 15.24,66.04 17.14,66.04 19.05,66.04 15.24,64.14 15.24,62.23 15.24,60.33 17.14,60.33 19.05,60.33 20.95,60.33 22.86,60.33 22.86,62.23 22.86,66.04 22.86,64.14 20.95,66.04 19.05,64.14 17.14,64.14 17.14,62.23 19.05,62.23 20.95,64.14 20.95,62.23
  pour Top (no thermals): 33.02,46.99 25.4,46.99 25.4,55.24 24.13,56.52 12.06,56.52 12.06,71.12 23.5,71.12 23.5,59.69 24.13,59.05 33.02,59.05
  pour Bottom (isolate 0.61, no thermals): 26.67,70.17 0,70.17 0,57.47 26.67,57.47
V1H
  Top 0.254: IC211.1 42.55,44.45 43.81,43.18 48.26,43.18 48.9,43.81 48.9,45.09 50.16,46.35 56.52,46.35 59.05,48.9 72.75,48.9 IC101.18
V1L
  Top 0.254: IC211.2 42.23,45.72 44.13,43.81 47.62,43.81 48.26,44.45 48.26,45.72 49.53,46.99 55.88,46.99 58.42,49.53 72.68,49.53 IC101.17
V1O
  Top 0.305: J_V1.P$2 45.72,51.75 45.72,48.26 45.09,47.62 44.77,47.62 44.42,47.28 IC212.5
  pour Top (no thermals): 36.83,59.05 36.83,50.8 47.62,50.8 47.62,59.05
V2  (via drill 0.61 pad 0.81)
  Top 0.305: IC242.4 116.52,65.09 118.11,63.5 124.78,63.5 125.73,62.55 127.32,62.55 127.32,61.28 R244.P$1
  Top 0.61: IC241.6 127.41,66.67 C242.1
  other vias: 137.16,45.72 139.06,45.72 140.97,45.72 142.88,45.72 144.78,45.72 146.69,45.72 146.69,47.62 146.69,49.53 146.69,51.44 146.69,53.34 144.78,47.62 142.88,47.62 140.97,47.62 144.78,49.53 144.78,51.44 144.78,53.34 142.88,53.34 140.97,53.34 139.06,53.34 137.16,53.34 137.16,51.44 137.16,47.62 137.16,49.53 139.06,47.62 140.97,49.53 142.88,49.53 142.88,51.44 140.97,51.44 139.06,49.53 139.06,51.44
  pour Top (no thermals): 127,66.67 134.62,66.67 134.62,58.42 135.89,57.15 147.96,57.15 147.96,42.55 136.53,42.55 136.53,53.98 135.89,54.61 127,54.61
  pour Bottom (isolate 0.61, no thermals): 133.35,43.18 160.02,43.18 160.02,56.2 133.35,56.2
V2H
  Top 0.254: IC101.38 88.58,51.12 108.58,51.12 109.22,51.75 109.22,68.26 110.17,69.22 IC241.1
V2L
  Top 0.254: IC101.37 88.51,50.48 109.22,50.48 109.86,51.12 109.86,67.94 110.49,68.58 117.16,68.58 117.79,67.94 IC241.2
V2O
  Top 0.305: J_V2.P$4 114.3,61.91 114.3,65.41 114.94,66.04 115.25,66.04 115.57,66.36 115.57,66.99 IC242.5
  pour Top (no thermals): 123.19,54.61 112.39,54.61 112.39,62.87 123.19,62.87
VCC  (via drill 0.41 pad 0.81)  (1 unrouted)
  Top 0.254: v78.11,54.61 75.64,54.61 IC101.14 73.42,52.39 v71.75,52.39 | v80.64,52.7 80.64,52.55 | IC101.44 87,56.95 v87,58.42 | IC101.54 87.64,60.96 v86.36,60.96 | IC101.34 83.19,53.69 83.19,54.61 v83.82,55.24 82.87,56.2 | IC101.74 79.85,67.31 v79.38,67.31 | IC101.83 77.19,66.04 v78.74,66.04 | IC101.64 84.38,64.77 v82.55,64.77 | C307.+ 67.69,43.2 | IC103.5 57.48,81.93 58.1,82.55 58.1,84.14 57.78,84.45 57.78,85.41 v56.83,86.36 | IC104.5 60.02,81.93 60.64,82.55 60.64,84.14 60.33,84.45 60.33,85.41 v59.37,86.36 | IC105.5 62.56,81.93 63.18,82.55 63.18,84.14 62.87,84.45 62.87,85.41 v61.91,86.36 | IC106.5 65.1,81.93 65.72,82.55 65.72,84.14 65.41,84.45 65.41,85.41 v64.45,86.36 | IC107.5 67.64,81.93 68.26,82.55 68.26,84.14 67.94,84.45 67.94,85.41 v66.99,86.36 | IC108.5 70.18,81.93 70.8,82.55 70.8,85.09 v69.53,86.36 | IC203.5 59.39,52.72 v59.69,53.02 | v59.69,55.56 59.37,55.24 58.65,55.24 IC213.5 | v59.69,58.1 59.69,57.78 58.65,57.78 IC2.5 | IC233.5 100.97,65 v100.97,67.31 103.5,67.31 | 103.5,67.31 103.49,67.3 IC243.5 | IC253.5 106.05,65 106.05,67.31 103.5,67.31 | IC101.24 79.92,51.82 79.92,51.98 | R115.2 89.85,42.76 89.85,41.59
  Top 0.305: R107.2 50.38,90.59 50.8,90.17 v50.8,87 48.26,84.45 v48.26,77.15 | 111.44,36.51 111.76,36.5 111.76,21.91 112.08,21.59 R307.2 | IC102.2 102.29,41.63 102.25,41.59 | IC102.10 97.09,41.64 97.04,41.59 | IC305.2 79.09,26.07 78.74,25.72 76.52,25.72 v74.93,27.3 | R308.2 R311.2 73.98,44.03 73.98,42.86
  Top 0.406: IC202.3 47.94,20 v48.58,20 48.58,33.97 47.62,34.92 v47.62,42.23 v55.24,42.23 | IC212.3 v48.26,48.58 v48.26,69.22 | IC222.3 48.58,77.15 v48.26,77.15 | v111.44,89.22 IC252.3 | v111.44,89.22 | 80.64,54.61 v78.11,54.61 | 80.64,54.61 v80.64,52.7 79.92,51.98 79.92,48.17 78.74,46.99 78.74,44.22 78.65,44.13 | 86.04,59.37 v87,58.42 | 86.04,59.37 85.41,60.01 | 85.41,60.01 v86.36,60.96 | 85.41,60.01 81.6,63.82 | 81.6,63.82 79.38,66.04 | 79.38,66.04 v78.74,66.04 | 79.38,66.04 v79.38,67.31 | 81.6,63.82 v82.55,64.77 | 86.04,59.37 82.87,56.2 81.28,54.61 80.64,54.61 | IC242.3 v111.13,65.09 v111.12,65.09 v111.12,51.44 | IC232.3 111.44,36.51 111.12,36.83 v111.12,48.26 v100.97,48.26 105.09,48.26 105.09,43.18 103.5,41.59 102.25,41.59 97.04,41.59 89.85,41.59 86.04,41.59 80.96,36.51 75.88,36.51 v74.93,35.56 71.12,31.75 66.04,31.75 | v111.44,89.22 111.44,83.5 111.76,83.19 v111.76,71.75 | 80.43,44.23 R312.2 | 80.43,44.23 79.69,44.13 78.65,44.13 | 78.65,44.13 77.38,42.86 73.98,42.86 68.03,42.86 C307.+ 67.22,42.86 63.18,42.86 63.18,43.79 IC303.5 63.15,42.52 62.87,42.23 v58.42,42.23 58.42,31.75 | 58.42,31.75 66.04,31.75 | J104.4 66.12,31.84 66.04,31.75 | 58.42,31.75 C118.2 | 80.43,44.23 R118.2
  Top 0.61: J100.P$38 101.6,92.71 v102.87,92.71 104.14,92.71 J100.P$40
  Bottom 0.254: 80.64,50.53 C105.2 | 76.91,53.41 C108.2 | v83.82,55.24 83.96,55.24 | 87.56,57.86 C102.2 | 83.89,66.11 C104.2 | v50.8,87 56.2,87 v56.83,86.36 v59.37,86.36 v61.91,86.36 v64.45,86.36 v66.99,86.36 v69.53,86.36 | v59.69,53.02 v59.69,55.56 v59.69,58.1
  Bottom 0.305: v100.97,48.26 v100.97,67.31 | v74.93,35.56 v74.93,27.3
  Bottom 0.406: v48.26,69.22 48.26,70.48 | 48.26,70.48 v48.26,77.15 | v111.44,89.22 111.44,92.08 110.81,92.71 v102.87,92.71 | v78.11,54.61 76.91,53.41 | 83.96,55.24 C106.2 | v87,58.42 87.56,57.86 | v86.36,60.96 86.63,60.69 C103.2 | v79.38,67.31 79.01,67.67 C101.2 | C107.2 78.25,66.04 v78.74,66.04 | v82.55,64.77 83.89,66.11 | C105.2 80.96,50.12 | v80.64,52.7 80.64,50.53 | v111.12,48.26 v111.12,51.44 | v48.26,48.58 48.26,42.86 v47.62,42.23 | 48.26,70.48 v51.44,70.48 | v111.12,65.09 113.03,66.99 113.03,70.48 v111.76,71.75 | v55.24,42.23 v58.42,42.23 58.42,42.55 57.78,43.18 57.78,50.16 59.69,52.07 v59.69,53.02
VS  (via drill 0.61 pad 0.81)
  Top 0.203: J301.P$4 69.85,6.35 70.48,5.71
  Top 0.305: v17.14,49.53 T211.D | v17.14,20.95 T201.D | T221.D v19.05,78.11
  Top 0.406: T241.D v142.88,64.14 | v142.88,35.56 T231.D
  Top 0.61: 67.94,18.41 67.31,17.78 J301.P$6
  Top 1.016: 153.67,35.56 153.99,35.56 154.31,35.24 | v146.69,67.94 152.4,67.94 154.31,66.04 | 5.71,53.34 v13.34,53.34 | 5.71,78.11 6.35,78.11 | 6.35,20.95 6.35,20.32 5.71,19.68
  Top 10.16: 18.41,5.71 70.48,5.71 143.51,5.71 | v17.14,49.53 T211.D | 5.71,18.41 5.71,19.68 5.71,53.34 5.71,78.11 | 154.31,16.51 154.31,35.24 154.31,66.04 154.31,78.11 | v17.14,20.95 T201.D | v142.88,35.56 T231.D | T241.D v142.88,64.14
  Top 11.176: 6.35,20.95 v17.14,20.95 | 6.35,78.11 T221.D | 6.67,49.53 v17.14,49.53 | 153.67,35.56 v142.88,35.56 | v142.88,64.14 153.35,64.14
  other vias: 22.86,81.92 20.95,81.92 19.05,81.92 17.14,81.92 15.24,81.92 13.34,81.92 13.34,80.01 13.34,78.11 13.34,76.2 13.34,74.3 15.24,80.01 17.14,80.01 19.05,80.01 15.24,78.11 15.24,76.2 15.24,74.3 17.14,74.3 19.05,74.3 20.95,74.3 22.86,74.3 22.86,76.2 22.86,80.01 22.86,78.11 20.95,80.01 17.14,78.11 17.14,76.2 19.05,76.2 20.95,78.11 20.95,76.2 22.86,53.34 20.95,53.34 19.05,53.34 17.14,53.34 15.24,53.34 13.34,51.44 13.34,49.53 13.34,47.62 13.34,45.72 15.24,51.44 17.14,51.44 19.05,51.44 15.24,49.53 15.24,47.62 15.24,45.72 17.14,45.72 19.05,45.72 20.95,45.72 22.86,45.72 22.86,47.62 22.86,51.44 22.86,49.53 20.95,51.44 19.05,49.53 17.14,47.62 19.05,47.62 20.95,49.53 20.95,47.62 22.86,24.77 20.95,24.77 19.05,24.77 17.14,24.77 15.24,24.77 13.34,24.77 13.34,22.86 13.34,20.95 13.34,19.05 13.34,17.14 15.24,22.86 17.14,22.86 19.05,22.86 15.24,20.95 15.24,19.05 15.24,17.14 17.14,17.14 19.05,17.14 20.95,17.14 22.86,17.14 22.86,19.05 22.86,22.86 22.86,20.95 20.95,22.86 19.05,20.95 17.14,19.05 19.05,19.05 20.95,20.95 20.95,19.05 137.16,31.75 139.06,31.75 140.97,31.75 142.88,31.75 144.78,31.75 146.69,31.75 146.69,33.66 146.69,35.56 146.69,37.47 146.69,39.37 144.78,33.66 142.88,33.66 140.97,33.66 144.78,35.56 144.78,37.47 144.78,39.37 142.88,39.37 140.97,39.37 139.06,39.37 137.16,39.37 137.16,37.47 137.16,33.66 137.16,35.56 139.06,33.66 140.97,35.56 142.88,37.47 140.97,37.47 139.06,35.56 139.06,37.47 137.16,60.33 139.06,60.33 140.97,60.33 142.88,60.33 144.78,60.33 146.69,60.33 146.69,62.23 146.69,64.14 146.69,66.04 144.78,62.23 142.88,62.23 140.97,62.23 144.78,64.14 144.78,66.04 144.78,67.94 142.88,67.94 140.97,67.94 139.06,67.94 137.16,67.94 137.16,66.04 137.16,62.23 137.16,64.14 139.06,62.23 140.97,64.14 142.88,66.04 140.97,66.04 139.06,64.14 139.06,66.04 137.16,88.9 139.06,88.9 140.97,88.9 142.88,88.9 144.78,88.9 146.69,88.9 146.69,90.81 146.69,92.71 146.69,94.61 146.69,96.52 144.78,90.81 142.88,90.81 140.97,90.81 144.78,92.71 144.78,94.61 144.78,96.52 142.88,96.52 140.97,96.52 139.06,96.52 137.16,96.52 137.16,94.61 137.16,90.81 137.16,92.71 139.06,90.81 140.97,92.71 142.88,92.71 142.88,94.61 140.97,94.61 139.06,92.71 139.06,94.61
  pour Top (no thermals): 64.14,19.68 64.14,12.7 62.23,10.79 62.23,1.27 74.93,1.27 74.93,10.79 73.03,12.7 73.03,19.68
  pour Top (isolate 0.61): 132.08,1.27 158.75,1.27 158.75,19.68 149.86,19.68 149.86,15.24 147.96,13.34 136.53,13.34 132.08,8.89
  pour Top (isolate 0.61, no thermals): 27.94,1.27 1.27,1.27 1.27,19.68 10.16,19.68 10.16,16.19 11.11,15.24 23.18,15.24 29.53,8.89
  pour Top (isolate 0.61, no thermals): 149.86,74.3 149.86,83.82 146.05,87.63 136.84,87.63 136.84,98.42 158.75,98.42 158.75,74.3
  pour Bottom (isolate 0.61, no thermals): 26.67,84.77 0,84.77 0,71.44 26.67,71.44
  pour Bottom (isolate 0.61, no thermals): 26.67,56.2 0,56.2 0,43.5 26.67,43.5
  pour Bottom (isolate 0.61, no thermals): 26.04,27.62 10.79,27.62 10.79,14.29 0,14.29 0,-0.32 39.37,-0.32 39.37,1.91 26.04,15.24
  pour Bottom (isolate 0.61, no thermals): 133.35,28.89 160.02,28.89 160.02,41.91 133.35,41.91
  pour Bottom (isolate 0.61, no thermals): 133.35,57.47 160.02,57.47 160.02,70.48 133.35,70.48
  pour Bottom (isolate 0.61, no thermals): 133.35,86.04 160.02,86.04 160.02,99.38 133.35,99.38
W1  (via drill 0.61 pad 0.81)
  Top 0.305: IC222.4 43.5,77.15 41.91,78.74 35.56,78.74 34.92,79.38 32.38,79.38 | 32.38,78.11 32.38,79.38 | 32.38,79.38 R224.P$1
  Top 0.61: IC221.6 32.62,75.56 C222.1
  other vias: 22.86,96.52 22.86,94.61 22.86,92.71 22.86,90.81 22.86,88.9 20.95,88.9 19.05,88.9 17.14,88.9 15.24,88.9 13.34,88.9 13.34,90.81 13.34,92.71 15.24,90.81 17.14,90.81 19.05,90.81 20.95,90.81 20.95,92.71 19.05,92.71 17.14,92.71 15.24,92.71 20.95,94.61 19.05,94.61 17.14,94.61 15.24,94.61 13.34,94.61 20.95,96.52 19.05,96.52 17.14,96.52 15.24,96.52 13.34,96.52
  pour Top (no thermals): 33.02,75.56 25.4,75.56 25.4,83.82 24.13,85.09 12.06,85.09 12.06,98.42 23.5,98.42 23.5,88.27 24.13,87.63 33.02,87.63
  pour Top (isolate 0.61, no thermals): 13.34,85.27 0.64,85.27 0.64,98.25 13.34,98.25
  pour Bottom (isolate 0.61, no thermals): 26.67,86.04 0,86.04 0,99.69 26.67,99.69
W1H
  Top 0.254: IC101.16 72.61,50.16 57.78,50.16 55.24,47.62 50.48,47.62 49.21,48.9 49.21,69.85 47.94,71.12 44.45,71.12 42.55,73.03 IC221.1
W1L
  Top 0.254: IC221.2 42.23,74.3 44.77,71.75 48.58,71.75 49.85,70.48 49.85,49.53 51.12,48.26 54.61,48.26 57.15,50.8 72.53,50.8 IC101.15
W1O
  Top 0.305: J_W1.P$2 46.04,80.64 45.72,80.64 45.72,76.83 45.09,76.2 44.77,76.2 44.42,75.85 IC222.5
  pour Top (no thermals): 36.83,87.63 36.83,79.38 47.62,79.38 47.62,87.63
W2  (via drill 0.61 pad 0.81)
  Top 0.406: C252.1 127.64,92.71 113.67,92.71 113.03,93.34 112.39,93.34 111.76,93.98 111.47,93.98 IC252.4 111.73,94.01
  Top 0.61: IC251.6 127.41,95.25 C252.1
  other vias: 137.16,74.3 139.06,74.3 140.97,74.3 142.88,74.3 144.78,74.3 146.69,74.3 146.69,76.2 146.69,78.11 146.69,80.01 146.69,81.92 144.78,76.2 142.88,76.2 140.97,76.2 144.78,78.11 144.78,80.01 144.78,81.92 142.88,81.92 140.97,81.92 139.06,81.92 137.16,81.92 137.16,80.01 137.16,76.2 137.16,78.11 139.06,76.2 140.97,78.11 142.88,78.11 142.88,80.01 140.97,80.01 139.06,78.11 139.06,80.01
  pour Top (no thermals): 127,95.25 134.62,95.25 134.62,87 135.89,85.72 145.41,85.72 147.96,83.19 147.96,71.12 136.53,71.12 136.53,82.55 135.89,83.19 127,83.19
  pour Bottom (isolate 0.61, no thermals): 133.35,71.75 160.02,71.75 160.02,84.77 133.35,84.77
W2H  (via drill 0.41 pad 0.81)
  Top 0.254: IC101.40 88.73,52.39 93.98,52.39 97.79,56.2 97.79,80.64 103.5,86.36 106.05,86.36 107.31,87.63 v107.31,96.52
  Top 0.305: v121.28,97.47 120.97,97.79 IC251.1
  Bottom 0.406: v121.28,97.47 118.11,97.47 116.84,96.52 110.49,96.52 109.22,97.79 107.95,97.79 107.31,97.16 v107.31,96.52
W2L  (via drill 0.41 pad 0.81)
  Top 0.254: IC101.39 88.65,51.75 94.3,51.75 98.42,55.88 98.42,80.01 104.14,85.72 106.36,85.72 108.58,87.95 v108.58,96.52
  Top 0.406: IC251.2 120.65,96.52 v121.28,95.89
  Bottom 0.406: v121.28,95.89 109.22,95.89 v108.58,96.52
W2O
  Top 0.406: IC252.5 109.54,93.66 110.49,92.71 112.39,92.71 113.67,91.44 J_W2.P$4
  pour Top (no thermals): 123.19,83.82 112.39,83.82 112.39,92.08 123.19,92.08

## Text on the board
Top: Ernst Abrazzo | Aug. 2009 | REV | 2.0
